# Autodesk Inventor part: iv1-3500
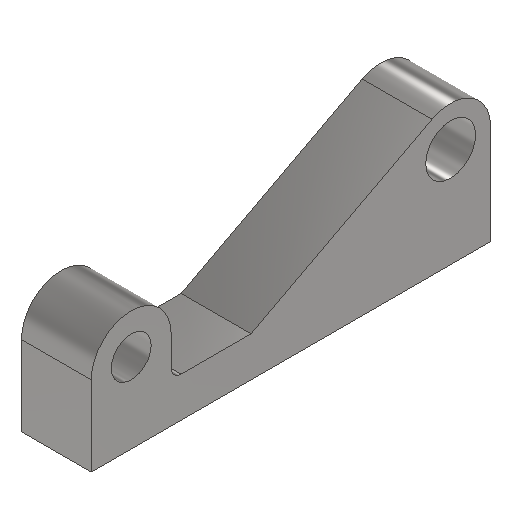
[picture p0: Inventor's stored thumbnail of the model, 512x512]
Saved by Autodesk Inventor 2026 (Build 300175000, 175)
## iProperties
Shininess: 64.0
Angle Display Precision: 2
Document Length Units: 11269
Document Angle Units: 11279
Document Time Units: 11290
Document Mass Units: 11283
Document Length Units Precision: 3
Document Angle Units Precision: 2
Compacted: True
Created: 2002-05
Part Number: iv1-3500
Document SubType Name: Modeling
Designer: Lars Bertram Pedersen
Material: Steel, Mild
Density: 7.85 g/cm^3
Appearance: Semi-Polished
Density: 0.0
Volumn: 0.0
Area: 0.0
PropertySet Name: Model Information
Control State: 0
Master: False
Checked Out: False
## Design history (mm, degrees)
sketch "Sketch1"
  geometry: L1 (0, 50)-(0, 0); L2 (0, 0)-(200, 0); L3 (200, 0)-(200, 40); L4 (155, 20)-(120, 20); L5 (120, 20)-(29.31, 67.701); L6 (160, 40)-(160, 25); C1 r 12.5 at (20, 50); C2 r 10 at (180, 40); A1 r 20 centre (20, 50) between (29.31, 67.701) and (0, 50); A2 r 20 centre (180, 40) between (200, 40) and (160, 40); A3 r 20 centre (180, 40) between (200, 40) and (160, 40); A4 r 5 centre (155, 25) between (155, 20) and (160, 25); 2 further points
  constraints: 12 end point, 8 point on circle, 6 centre point, 6 tangent, 3 coincident, 2 equal radius, 2 parallel, 2 perpendicular, 2 point on line, 1 vertical
  dimensions: "d9" = 200 distance of L1.end L2.end; "d15" = 25 diameter of C1; "d18" = 20 diameter of C2; "d22" = 50 distance from line of A1.centre L2; "d24" = 100 horizontal distance of A1.centre L4.end; "d26" = 20 distance between parallel lines of L2 L4; "d31" = 20 radius of A2 (derived); "d34" = 40 distance from line of L2 A3.centre; "d37" = 5 radius of A4
extrude "Extrusion1" new body sketch "Sketch1" distance "d27" = 35; taper "d28" = 0 deg
body "Solid1"
